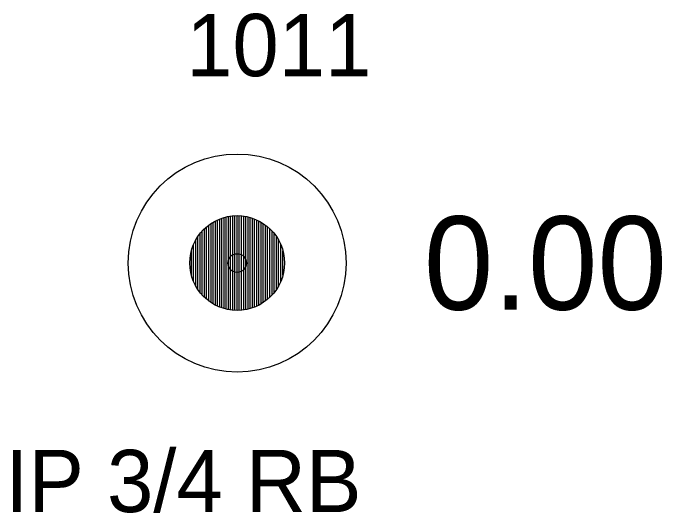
# Model space of a CAD drawing. Extents: x 1538847 to 1546108, y 887169 to 888935.
# Drawn here: x 1546052.75 to 1546063.18, y 888101.28 to 888109.31 of the extents above; entities that cross this region are included whole.
import ezdxf

# ---------------------------------------------------------------- set-up
doc = ezdxf.new("R2010")
doc.units = 0
for name, color, linetype in [('RD_EX_DV_Prop_txCode', 7, 'Continuous'), ('RD_EX_DV_PropPin', 7, 'Continuous'), ('RD_EX_TX_DV_Prop_ELEV', 7, 'Continuous'), ('RD_SMD_Locator', 7, 'Continuous')]:
    doc.layers.add(name, color=color, linetype=linetype)

msp = doc.modelspace()

# ---------------------------------------------------------------- linework, layer by layer
at = {"layer": 'RD_EX_DV_PropPin'}
for p, q in [((1546056.039, 888104.6), (1546056.039, 888105.986)), ((1546056.074, 888104.585), (1546056.074, 888106)), ((1546056.109, 888104.572), (1546056.109, 888106.013)), ((1546056.144, 888104.561), (1546056.144, 888106.024)), ((1546056.179, 888104.552), (1546056.179, 888106.034)), ((1546056.214, 888104.545), (1546056.214, 888106.041)), ((1546056.249, 888104.539), (1546056.249, 888106.047)), ((1546056.284, 888104.535), (1546056.284, 888106.051)), ((1546056.319, 888104.533), (1546056.319, 888106.053)), ((1546056.354, 888104.532), (1546056.354, 888106.054)), ((1546056.389, 888104.533), (1546056.389, 888106.053)), ((1546056.424, 888104.535), (1546056.424, 888106.051)), ((1546056.459, 888104.539), (1546056.459, 888106.047)), ((1546056.494, 888104.545), (1546056.494, 888106.041)), ((1546056.529, 888104.552), (1546056.529, 888106.034)), ((1546056.564, 888104.561), (1546056.564, 888106.024)), ((1546056.599, 888104.572), (1546056.599, 888106.013)), ((1546056.634, 888104.585), (1546056.634, 888106)), ((1546056.669, 888104.6), (1546056.669, 888105.986)), ((1546055.864, 888104.711), (1546055.864, 888105.875)), ((1546055.899, 888104.683), (1546055.899, 888105.903)), ((1546055.934, 888104.658), (1546055.934, 888105.927)), ((1546055.969, 888104.637), (1546055.969, 888105.949)), ((1546056.004, 888104.617), (1546056.004, 888105.969)), ((1546056.704, 888104.617), (1546056.704, 888105.969)), ((1546056.739, 888104.637), (1546056.739, 888105.949)), ((1546056.774, 888104.658), (1546056.774, 888105.927)), ((1546056.809, 888104.683), (1546056.809, 888105.903)), ((1546056.844, 888104.711), (1546056.844, 888105.875)), ((1546055.759, 888104.819), (1546055.759, 888105.767)), ((1546055.794, 888104.778), (1546055.794, 888105.808)), ((1546055.829, 888104.742), (1546055.829, 888105.844)), ((1546056.879, 888104.742), (1546056.879, 888105.844)), ((1546056.914, 888104.778), (1546056.914, 888105.808)), ((1546056.949, 888104.819), (1546056.949, 888105.767)), ((1546055.689, 888104.923), (1546055.689, 888105.662)), ((1546055.724, 888104.866), (1546055.724, 888105.719)), ((1546056.984, 888104.866), (1546056.984, 888105.719)), ((1546057.019, 888104.923), (1546057.019, 888105.662)), ((1546055.653, 888104.995), (1546055.653, 888105.591)), ((1546057.054, 888104.995), (1546057.054, 888105.591)), ((1546055.618, 888105.097), (1546055.618, 888105.489)), ((1546057.089, 888105.097), (1546057.089, 888105.489))]:
    msp.add_line(p, q, dxfattribs=at)
for radius in [1.75, 0.761]:
    msp.add_circle((1546056.354, 888105.293), radius, dxfattribs=at)
at = {"layer": 'RD_SMD_Locator'}
msp.add_circle((1546056.354, 888105.293), 0.15, dxfattribs=at)

# ---------------------------------------------------------------- texts
at = {"layer": 'RD_EX_DV_Prop_txCode'}
for s, p in [('1011', (1546055.535, 888108.293)), ('IP 3/4 RB', (1546052.629, 888101.293))]:
    msp.add_text(s, height=1, dxfattribs=at).set_placement(p)
at = {"layer": 'RD_EX_TX_DV_Prop_ELEV'}
msp.add_text('0.00', height=1.5, dxfattribs=at).set_placement((1546059.354, 888104.543))

doc.saveas('drawing.dxf')
